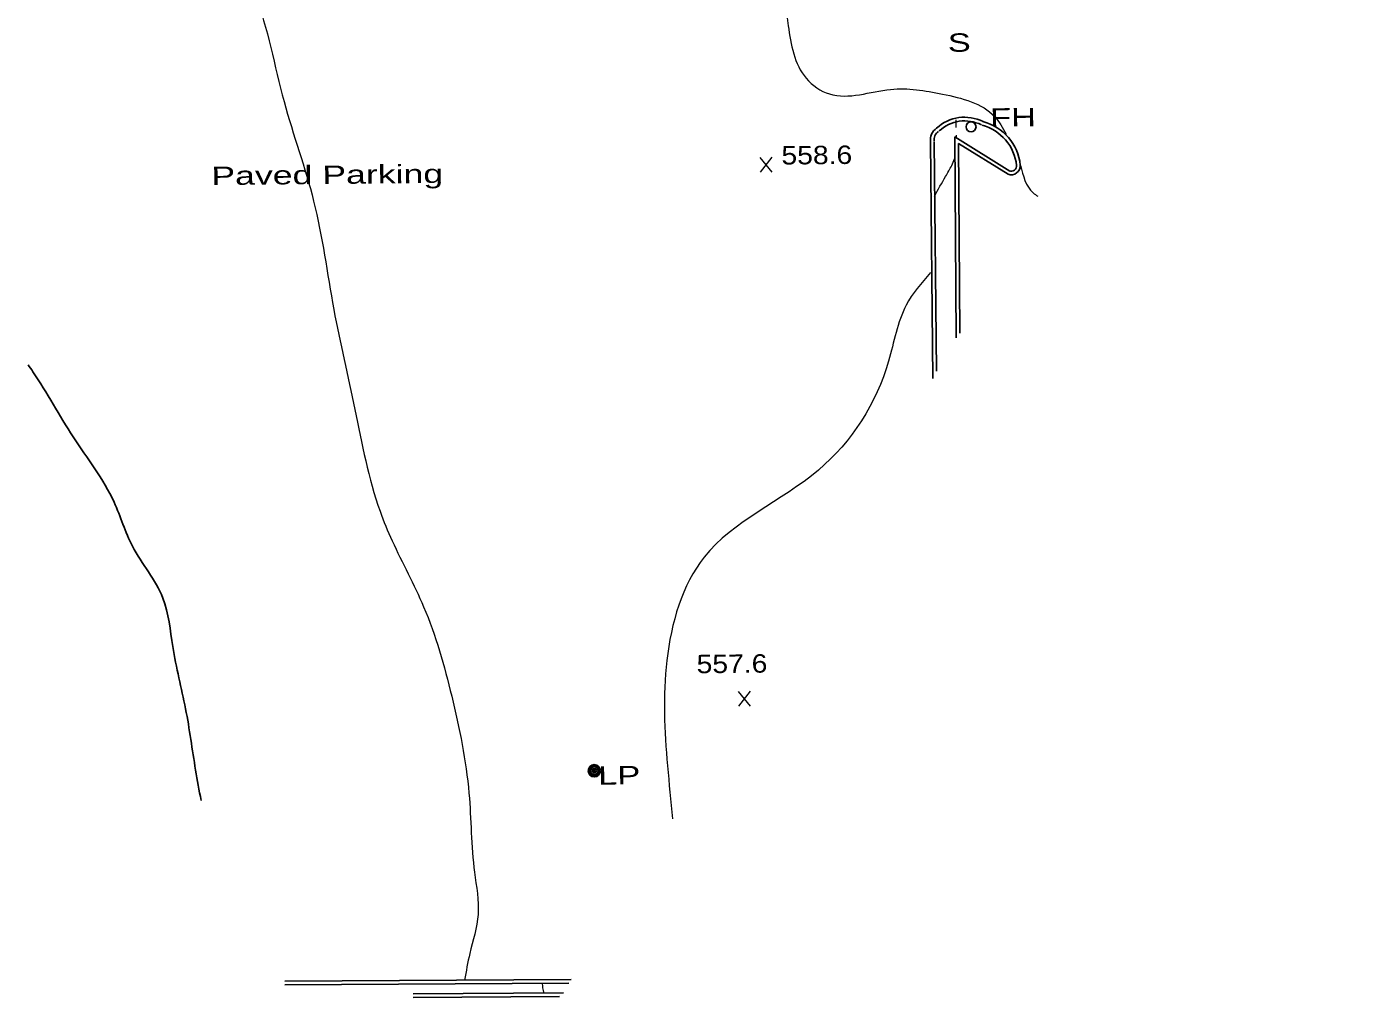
# Model space of a CAD drawing. Extents: x 2361708 to 2370558, y 6977955 to 6991887.
# Drawn here: x 2367134.3 to 2367480.2, y 6987695.9 to 6987949.5 of the extents above; entities that cross this region are included whole.
import ezdxf

# ---------------------------------------------------------------- set-up
doc = ezdxf.new("R2010")
doc.units = 0
doc.header["$LTSCALE"] = 1.9
for name, color, linetype, lineweight in [('13', 7, 'Continuous', 13), ('2', 7, 'Continuous', 25), ('20', 7, 'Continuous', 25), ('21', 7, 'Continuous', 25), ('31', 7, 'Continuous', 13), ('35', 7, 'Continuous', 13)]:
    doc.layers.add(name, color=color, linetype=linetype, lineweight=lineweight)

msp = doc.modelspace()

# ---------------------------------------------------------------- linework, layer by layer
at = {"layer": '13'}
for p, q in [((2367376.84, 6987925.076), (2367376.899, 6987923.077)), ((2367376.948, 6987921.077), (2367376.964, 6987920.517))]:
    msp.add_line(p, q, dxfattribs=at)
at = {"layer": '2'}
for p, q in [((2367370.275, 6987919.333), (2367370.852, 6987857.556)), ((2367371.235, 6987919.342), (2367371.795, 6987859.435)), ((2367276.482, 6987700.61), (2367201.722, 6987700.179)), ((2367275.801, 6987699.644), (2367201.732, 6987699.219)), ((2367235.206, 6987696.897), (2367274.455, 6987697.131)), ((2367235.215, 6987695.937), (2367273.384, 6987696.16))]:
    msp.add_line(p, q, dxfattribs=at)
for points in [[(2367376.982, 6987868.135), (2367376.613, 6987920.624), (2367390.998, 6987911.691)], [(2367377.94, 6987869.424), (2367377.589, 6987918.893), (2367390.496, 6987910.876)]]:
    msp.add_lwpolyline(points, dxfattribs=at)
for centre, radius, start, end in [((2367379.167, 6987915.113), 10.661, 63.25235, 133.25289), ((2367379.167, 6987915.113), 9.701, 63.25235, 133.25289), ((2367380.527, 6987911.831), 12.296, 6.30136, 74.97089), ((2367380.527, 6987911.831), 13.256, 6.30136, 74.97089), ((2367373.751, 6987919.906), 3.522, 122.44752, 189.35805), ((2367373.751, 6987919.906), 2.562, 122.44752, 189.35805), ((2367391.309, 6987913.132), 2.399, 250.1936, 3.67468), ((2367391.309, 6987913.132), 1.439, 250.1936, 3.67468)]:
    msp.add_arc(centre, radius, start, end, dxfattribs=at)
at = {"layer": '20'}
for centre, radius in [((2367380.848, 6987923.264), 1.3), ((2367282.493, 6987755.14), 1.6), ((2367282.493, 6987755.14), 1.3), ((2367282.493, 6987755.14), 1), ((2367282.493, 6987755.14), 0.539), ((2367282.493, 6987755.14), 0.192)]:
    msp.add_circle(centre, radius, dxfattribs=at)
at = {"layer": '31'}
for p, q in [((2367328.928, 6987911.45), (2367325.811, 6987915.3)), ((2367325.848, 6987911.42), (2367328.891, 6987915.329)), ((2367323.265, 6987772.009), (2367320.148, 6987775.859)), ((2367320.185, 6987771.98), (2367323.228, 6987775.889))]:
    msp.add_line(p, q, dxfattribs=at)
at = {"layer": '31', "lineweight": 25}
msp.add_spline([(2367134.667, 6987861.158), (2367135.935, 6987859.33), (2367146.437, 6987842.309), (2367157.12, 6987825.27), (2367161.92, 6987813.765), (2367169.849, 6987800.24), (2367172.43, 6987787.544), (2367175.784, 6987771.335), (2367178.407, 6987755.309), (2367179.822, 6987747.412)], degree=3, dxfattribs=at)
at = {"layer": '35'}
for points in [[(2367219.993, 6988514.402), (2367223.924, 6988512.199), (2367225.343, 6988502.852), (2367217.797, 6988490.88), (2367209.959, 6988474.855), (2367200.736, 6988445.776), (2367191.453, 6988424.996), (2367180.067, 6988399.236), (2367165.913, 6988365.01), (2367160.003, 6988338.702), (2367150.355, 6988309.989), (2367148.359, 6988287.589), (2367149.255, 6988270.087), (2367148.144, 6988247.115), (2367147.307, 6988224.756), (2367146.224, 6988193.484), (2367143.901, 6988165.441), (2367141.565, 6988136.637), (2367137.942, 6988112.801), (2367135.328, 6988084.805), (2367137.393, 6988062.254), (2367138.292, 6988045.561), (2367144.845, 6988028.503), (2367151.824, 6988012.849), (2367167.451, 6987998.577), (2367181.01, 6987981.855), (2367193.919, 6987957.866), (2367201.496, 6987929.847), (2367209.224, 6987903.85), (2367214.483, 6987875.598), (2367219.983, 6987849.49), (2367226.546, 6987822.881), (2367229.709, 6987815.181), (2367237.924, 6987797.948), (2367245.266, 6987774.607), (2367249.768, 6987749.258), (2367251.204, 6987728.621), (2367252.159, 6987717.639), (2367249.976, 6987707.408), (2367248.643, 6987700.425)], [(2367145.501, 6988378.686), (2367145.739, 6988370.568), (2367142.467, 6988358.157), (2367137.425, 6988343.578), (2367130.831, 6988321.934), (2367125.926, 6988301.476), (2367119.431, 6988279.833), (2367115.023, 6988258.54), (2367106.408, 6988227.587), (2367102.682, 6988188.229), (2367094.858, 6988153.943), (2367089.196, 6988117.378), (2367084.613, 6988085.083), (2367086.282, 6988061.077), (2367083.386, 6988029.138), (2367082.048, 6988001.554), (2367079.637, 6987967.009), (2367079.404, 6987942.036), (2367080.967, 6987922.82), (2367080.771, 6987888.856), (2367080.046, 6987868.379), (2367079.06, 6987851.129), (2367079.061, 6987843.678)], [(2367480.168, 6988335.65), (2367459.83, 6988331.046), (2367436.721, 6988324.545), (2367412.615, 6988316.666), (2367399.484, 6988313.54), (2367376.593, 6988308.222), (2367362.746, 6988303.6), (2367352.659, 6988298.114), (2367345.527, 6988284.525), (2367340.023, 6988278.623), (2367329.076, 6988262.538), (2367323.195, 6988241.571), (2367310.722, 6988224.011), (2367297.308, 6988208.573), (2367304.29, 6988173.727), (2367309.392, 6988147.315), (2367312.461, 6988122.193), (2367302.858, 6988094.08), (2367299.541, 6988065.407), (2367304.477, 6988033.303), (2367316.095, 6988011.532), (2367320.396, 6987989.282), (2367328.783, 6987970.781), (2367331.521, 6987960.497), (2367333.134, 6987949.641), (2367337.805, 6987935.945), (2367343.855, 6987931.843), (2367359.824, 6987933.055), (2367373.386, 6987931.814), (2367387.013, 6987925.943), (2367390.037, 6987921.341)], [(2367371.31, 6987905.133), (2367374.201, 6987910.321), (2367375.794, 6987913.176), (2367376.557, 6987914.913)], [(2367393.774, 6987913.207), (2367397.053, 6987906.037), (2367398.281, 6987905.139)], [(2367370.249, 6987885.201), (2367363.9, 6987876.681), (2367359.309, 6987862.106), (2367340.999, 6987833.641), (2367311.174, 6987810.926), (2367301.41, 6987783.941), (2367301.592, 6987756.432), (2367302.944, 6987742.584)], [(2367269.396, 6987696.972), (2367269.072, 6987698.489), (2367269, 6987699.729)]]:
    msp.add_spline(points, degree=3, dxfattribs=at)

# ---------------------------------------------------------------- texts
at = {"layer": '2', "width": 1.45}
msp.add_text('Paved Parking', height=4.8, rotation=0.545, dxfattribs=at).set_placement((2367182.523, 6987908.056))
at = {"layer": '20', "width": 1.4}
for s, p in [('  FH', (2367380.838, 6987923.254)), ('  LP', (2367278.528, 6987751.462))]:
    msp.add_text(s, height=4.8, rotation=0.545, dxfattribs=at).set_placement(p)
at = {"layer": '21', "width": 1.4}
msp.add_text('  S', height=4.8, rotation=0.545, dxfattribs=at).set_placement((2367369.802, 6987942.79))
at = {"layer": '31', "width": 1.15}
for s, p in [('558.6', (2367331.369, 6987913.413)), ('557.6', (2367309.223, 6987780.596))]:
    msp.add_text(s, height=4.8, rotation=0.545, dxfattribs=at).set_placement(p)

doc.saveas('drawing.dxf')
